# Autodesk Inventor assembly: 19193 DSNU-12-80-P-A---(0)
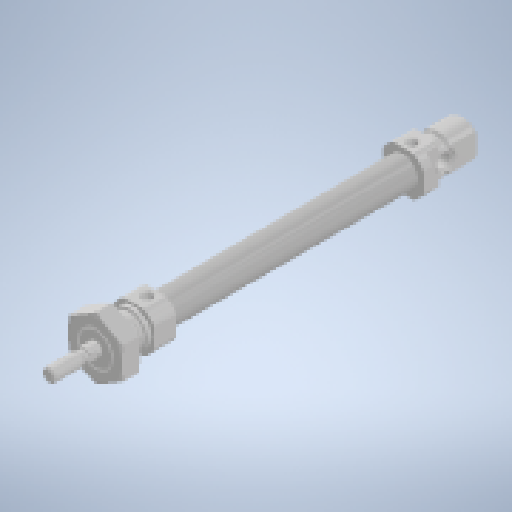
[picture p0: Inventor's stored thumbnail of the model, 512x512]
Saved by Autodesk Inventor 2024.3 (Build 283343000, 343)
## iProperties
Company: CADENAS
Created: 2024-11
Part Number: 19193 DSNU-12-80-P-A---(0)
Description: STEP AP214
Document SubType Name: Assembly
Designer: ruhr
Title: 19193_DSNU-12-80-P-A
Author: License CC BY-ND 4.0
Sending System: PARTsolutions
Preprocessor: ST-DEVELOPER v19.3
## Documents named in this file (5)
- C:\Users\ruhr\OneDrive - Mercantec\Dokumenter\DigiTwinVideo\PARTserver0202411291136211484952210e898ce\19193_DSNU-12-80-P-A\19193_DSNU-12-80-P-A\19193_DSNU-12-80-P-A.iam
- C:\Users\ruhr\OneDrive - Mercantec\Dokumenter\DigiTwinVideo\PARTserver0202411291136211484952210e898ce\19193_DSNU-12-80-P-A\19193_DSNU-12-80-P-A\19193 DSNU-12-80-P---(A----0-ZR).ipt
- C:\Users\ruhr\OneDrive - Mercantec\Dokumenter\DigiTwinVideo\PARTserver0202411291136211484952210e898ce\19193_DSNU-12-80-P-A\19193_DSNU-12-80-P-A\DIN-439-B - M16x1.5(F).ipt
- C:\Users\ruhr\OneDrive - Mercantec\Dokumenter\DigiTwinVideo\PARTserver0202411291136211484952210e898ce\19193_DSNU-12-80-P-A\19193_DSNU-12-80-P-A\19193 DSNU-12-80-P---(A---00--0-KS).ipt
- C:\Users\ruhr\OneDrive - Mercantec\Dokumenter\DigiTwinVideo\Pusherplate2.ipt
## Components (4 placed, 4 different names)
1. NAUO1
2. NAUO2
3. NAUO3 — Flush:1
4. Pusherplate2:1 — Flush:1
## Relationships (1: Flush 1)
- Flush:1: NAUO3 ↔ Pusherplate2:1
